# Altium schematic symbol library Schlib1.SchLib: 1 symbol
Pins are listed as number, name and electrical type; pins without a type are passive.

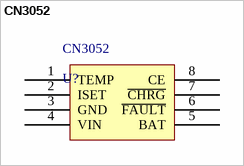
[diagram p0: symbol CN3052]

## CN3052
designator CN3052, comment U?
pins: 1 TEMP, 2 ISET, 3 GND, 4 VIN, 5 BAT, 6 ~{FAULT}, 7 ~{CHRG}, 8 CE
